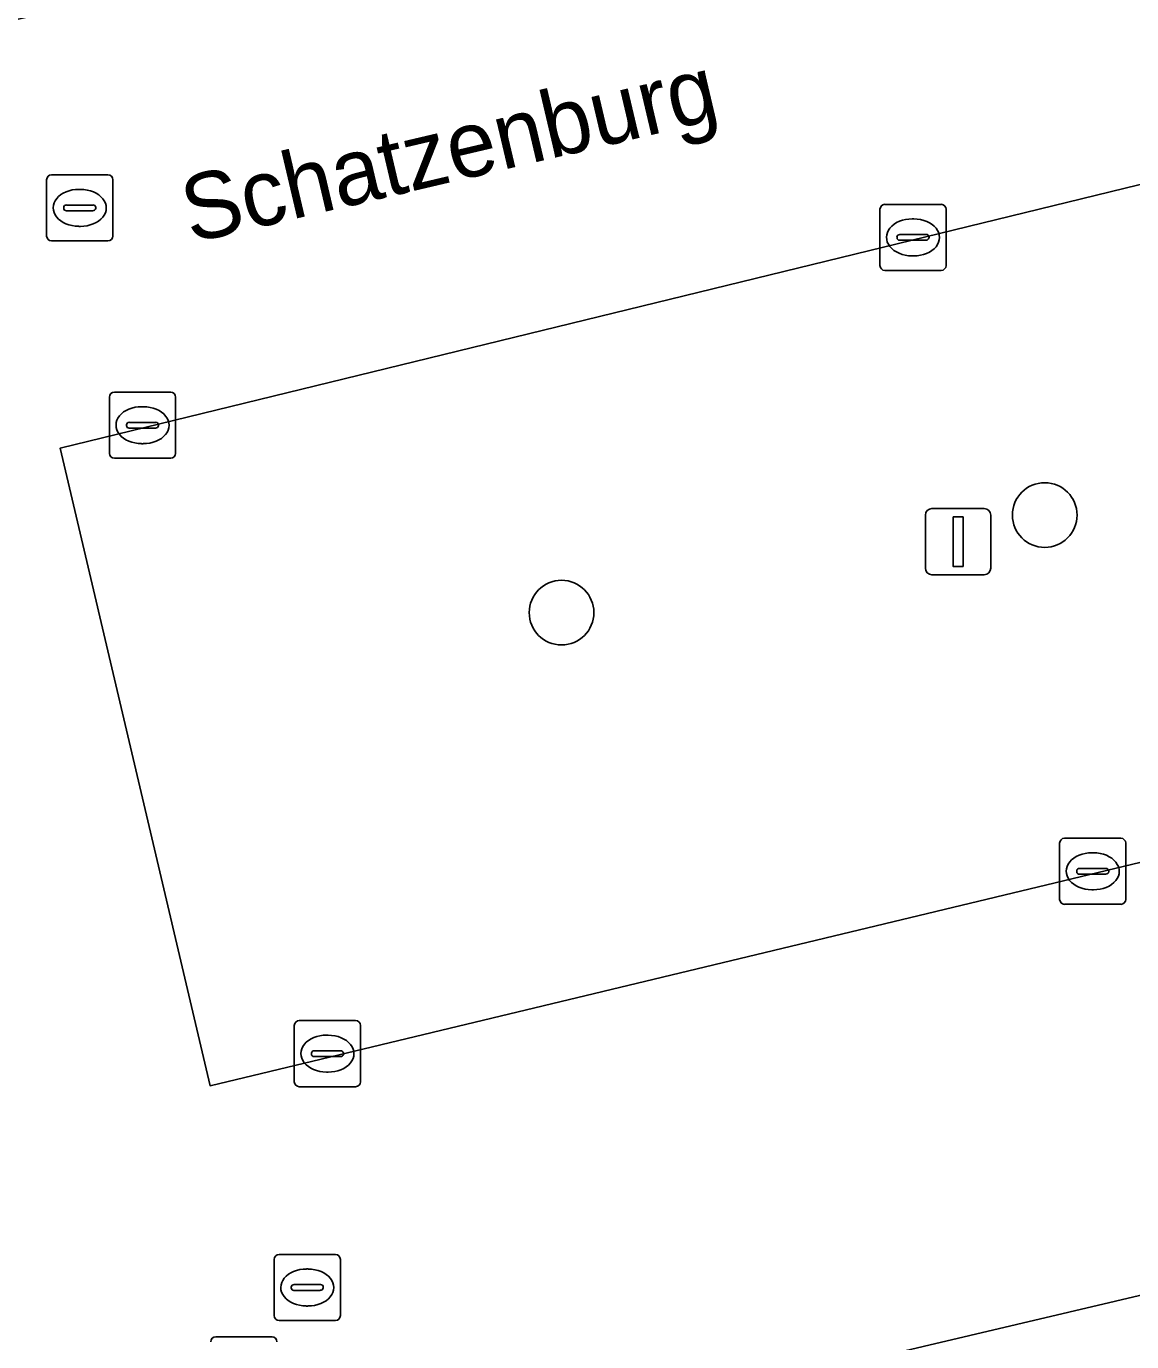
# Model space of a CAD drawing. Extents: x 158031 to 159244, y 380104 to 381214.
# Drawn here: x 158644.85 to 158661.57, y 380591.53 to 380611.43 of the extents above; entities that cross this region are included whole.
import ezdxf

# ---------------------------------------------------------------- set-up
doc = ezdxf.new("R2010")
doc.units = 0
for name, color, linetype in [('IMGEO_Boom', 7, 'Continuous'), ('IMGEO_Kolk', 7, 'Continuous'), ('IMGEO_Lichtmast', 7, 'Continuous'), ('IMGEO_Openbare_ruimte_label', 7, 'Continuous'), ('IMGEO_Parkeervlak_open', 7, 'Continuous'), ('IMGEO_Rijbaan_lokaal_open', 7, 'Continuous'), ('IMGEO_Rioolput', 7, 'Continuous'), ('IMGEO_Voetpad_open', 7, 'Continuous')]:
    doc.layers.add(name, color=color, linetype=linetype)

msp = doc.modelspace()

# ---------------------------------------------------------------- linework, layer by layer
at = {"layer": 'IMGEO_Boom'}
for centre in [(158660.256, 380604.036), (158652.948, 380602.56)]:
    msp.add_circle(centre, 0.489, dxfattribs=at)
at = {"layer": 'IMGEO_Kolk'}
for p, q in [((158657.838, 380608.737), (158658.69, 380608.737)), ((158657.763, 380607.811), (158657.763, 380608.663)), ((158658.251, 380608.517), (158658.276, 380608.517)), ((158658.764, 380608.663), (158658.764, 380607.811)), ((158658.022, 380608.231), (158658.022, 380608.243)), ((158658.46, 380608.194), (158658.062, 380608.194)), ((158658.065, 380608.28), (158658.463, 380608.28)), ((158658.506, 380608.243), (158658.506, 380608.231)), ((158658.274, 380607.957), (158658.249, 380607.957)), ((158658.69, 380607.737), (158657.838, 380607.737)), ((158646.11, 380604.97), (158646.11, 380605.822)), ((158646.185, 380605.896), (158647.037, 380605.896)), ((158647.111, 380605.822), (158647.111, 380604.97)), ((158646.598, 380605.676), (158646.623, 380605.676)), ((158646.369, 380605.39), (158646.369, 380605.402)), ((158646.807, 380605.353), (158646.409, 380605.353)), ((158646.412, 380605.439), (158646.81, 380605.439)), ((158646.853, 380605.402), (158646.853, 380605.39)), ((158646.621, 380605.116), (158646.596, 380605.116)), ((158647.037, 380604.896), (158646.185, 380604.896)), ((158660.481, 380598.221), (158660.481, 380599.073)), ((158660.556, 380599.147), (158661.408, 380599.147)), ((158661.482, 380599.073), (158661.482, 380598.221)), ((158660.969, 380598.927), (158660.994, 380598.927)), ((158660.74, 380598.641), (158660.74, 380598.653)), ((158661.178, 380598.604), (158660.78, 380598.604)), ((158660.783, 380598.69), (158661.181, 380598.69)), ((158661.224, 380598.653), (158661.224, 380598.641)), ((158660.992, 380598.367), (158660.967, 380598.367)), ((158661.408, 380598.147), (158660.556, 380598.147)), ((158648.981, 380596.388), (158649.833, 380596.388)), ((158648.906, 380595.462), (158648.906, 380596.314)), ((158649.907, 380596.314), (158649.907, 380595.462)), ((158649.394, 380596.168), (158649.419, 380596.168)), ((158649.165, 380595.882), (158649.165, 380595.894)), ((158649.603, 380595.845), (158649.205, 380595.845)), ((158649.208, 380595.931), (158649.606, 380595.931)), ((158649.649, 380595.894), (158649.649, 380595.882)), ((158649.417, 380595.608), (158649.392, 380595.608)), ((158649.833, 380595.388), (158648.981, 380595.388))]:
    msp.add_line(p, q, dxfattribs=at)
for points in [[(158657.838, 380608.737), (158658.69, 380608.737)], [(158657.763, 380607.811), (158657.763, 380608.663)], [(158658.764, 380608.663), (158658.764, 380607.811)], [(158658.69, 380607.737), (158657.838, 380607.737)], [(158646.11, 380604.97), (158646.11, 380605.822)], [(158646.185, 380605.896), (158647.037, 380605.896)], [(158647.111, 380605.822), (158647.111, 380604.97)], [(158647.037, 380604.896), (158646.185, 380604.896)], [(158660.481, 380598.221), (158660.481, 380599.073)], [(158660.556, 380599.147), (158661.408, 380599.147)], [(158661.482, 380599.073), (158661.482, 380598.221)], [(158661.408, 380598.147), (158660.556, 380598.147)], [(158648.981, 380596.388), (158649.833, 380596.388)], [(158648.906, 380595.462), (158648.906, 380596.314)], [(158649.907, 380596.314), (158649.907, 380595.462)], [(158649.833, 380595.388), (158648.981, 380595.388)]]:
    msp.add_lwpolyline(points, dxfattribs=at)
for centre, radius, start, end in [((158657.84, 380608.661), 0.0765, 91.552, 178.448), ((158657.84, 380608.661), 0.0765, 91.552, 178.448), ((158658.688, 380608.661), 0.0765, 1.552, 88.448), ((158658.688, 380608.661), 0.0765, 1.552, 88.448), ((158658.062, 380608.24), 0.0403, 85.8775, 175.7526), ((158658.059, 380608.23), 0.0366, 178.938, 274.7102), ((158658.463, 380608.237), 0.043, 264.8664, 352.4533), ((158658.467, 380608.242), 0.0386, 1.7309, 96.639), ((158657.84, 380607.813), 0.0765, 181.552, 268.448), ((158657.84, 380607.813), 0.0765, 181.552, 268.448), ((158658.688, 380607.813), 0.0765, 271.552, 358.448), ((158658.688, 380607.813), 0.0765, 271.552, 358.448), ((158646.187, 380605.82), 0.0765, 91.552, 178.448), ((158646.187, 380605.82), 0.0765, 91.552, 178.448), ((158647.035, 380605.82), 0.0765, 1.552, 88.448), ((158647.035, 380605.82), 0.0765, 1.552, 88.448), ((158646.409, 380605.399), 0.0403, 85.8775, 175.7526), ((158646.406, 380605.389), 0.0366, 178.938, 274.7102), ((158646.81, 380605.396), 0.043, 264.8664, 352.4533), ((158646.814, 380605.401), 0.0386, 1.7309, 96.639), ((158646.187, 380604.972), 0.0765, 181.552, 268.448), ((158646.187, 380604.972), 0.0765, 181.552, 268.448), ((158647.035, 380604.972), 0.0765, 271.552, 358.448), ((158647.035, 380604.972), 0.0765, 271.552, 358.448), ((158660.558, 380599.071), 0.0765, 91.552, 178.448), ((158660.558, 380599.071), 0.0765, 91.552, 178.448), ((158661.406, 380599.071), 0.0765, 1.552, 88.448), ((158661.406, 380599.071), 0.0765, 1.552, 88.448), ((158660.78, 380598.65), 0.0403, 85.8775, 175.7526), ((158660.777, 380598.64), 0.0366, 178.938, 274.7102), ((158661.181, 380598.647), 0.043, 264.8664, 352.4533), ((158661.185, 380598.652), 0.0386, 1.7309, 96.639), ((158660.558, 380598.223), 0.0765, 181.552, 268.448), ((158660.558, 380598.223), 0.0765, 181.552, 268.448), ((158661.406, 380598.223), 0.0765, 271.552, 358.448), ((158661.406, 380598.223), 0.0765, 271.552, 358.448), ((158648.983, 380596.312), 0.0765, 91.552, 178.448), ((158648.983, 380596.312), 0.0765, 91.552, 178.448), ((158649.831, 380596.312), 0.0765, 1.552, 88.448), ((158649.831, 380596.312), 0.0765, 1.552, 88.448), ((158649.205, 380595.891), 0.0403, 85.8775, 175.7526), ((158649.202, 380595.881), 0.0366, 178.938, 274.7102), ((158649.606, 380595.888), 0.043, 264.8664, 352.4533), ((158649.61, 380595.893), 0.0386, 1.7309, 96.639), ((158648.983, 380595.464), 0.0765, 181.552, 268.448), ((158648.983, 380595.464), 0.0765, 181.552, 268.448), ((158649.831, 380595.464), 0.0765, 271.552, 358.448), ((158649.831, 380595.464), 0.0765, 271.552, 358.448)]:
    msp.add_arc(centre, radius, start, end, dxfattribs=at)
for centre, major_axis, ratio, start_param, end_param in [((158658.25, 380608.237), (-0.387, 0.002), 0.722429, 4.712389, 7.853982), ((158658.275, 380608.237), (-0.39, 0.002), 0.717154, 1.570796, 4.712389), ((158646.597, 380605.396), (-0.387, 0.002), 0.722429, 4.712389, 7.853982), ((158646.622, 380605.396), (-0.39, 0.002), 0.717154, 1.570796, 4.712389), ((158660.968, 380598.647), (-0.387, 0.002), 0.722429, 4.712389, 7.853982), ((158660.993, 380598.647), (-0.39, 0.002), 0.717154, 1.570796, 4.712389), ((158649.393, 380595.888), (-0.387, 0.002), 0.722429, 4.712389, 7.853982), ((158649.418, 380595.888), (-0.39, 0.002), 0.717154, 1.570796, 4.712389)]:
    msp.add_ellipse(centre, major_axis=major_axis, ratio=ratio, start_param=start_param, end_param=end_param, dxfattribs=at)
at = {"layer": 'IMGEO_Lichtmast'}
for p, q in [((158658.451, 380603.234), (158658.451, 380604.034)), ((158658.451, 380604.034), (158658.451, 380603.234)), ((158658.551, 380604.134), (158659.341, 380604.134)), ((158659.341, 380604.134), (158658.551, 380604.134)), ((158659.441, 380604.034), (158659.441, 380603.234)), ((158659.441, 380603.234), (158659.441, 380604.034)), ((158659.341, 380603.134), (158658.551, 380603.134)), ((158658.551, 380603.134), (158659.341, 380603.134))]:
    msp.add_line(p, q, dxfattribs=at)
msp.add_lwpolyline([(158658.871, 380604.009), (158659.021, 380604.009), (158659.021, 380603.259), (158658.871, 380603.259), (158658.871, 380604.009)], dxfattribs=at)
for centre, start, end in [((158658.551, 380604.034), 90, 180), ((158658.551, 380604.034), 90, 180), ((158659.341, 380604.034), 0, 90), ((158659.341, 380604.034), 360, 90), ((158658.551, 380603.234), 180, 270), ((158658.551, 380603.234), 180, 270), ((158659.341, 380603.234), 270, 0), ((158659.341, 380603.234), 270, 0)]:
    msp.add_arc(centre, 0.1, start, end, dxfattribs=at)
at = {"layer": 'IMGEO_Parkeervlak_open'}
msp.add_lwpolyline([(158662.959, 380609.345), (158645.363, 380605.047), (158647.633, 380595.402), (158665.451, 380599.684)], dxfattribs=at)
at = {"layer": 'IMGEO_Rijbaan_lokaal_open'}
msp.add_lwpolyline([(158674.8, 380595.318), (158681.44, 380567.252), (158682.048, 380564.681), (158687.531, 380566.04), (158675.144, 380618.798), (158674.853, 380618.727), (158646.289, 380611.903), (158642.774, 380611.091), (158641.644, 380615.902), (158637.085, 380614.819), (158638.238, 380610.014), (158643.37, 380588.22), (158643.438, 380587.928)], close=True, dxfattribs=at)
msp.add_lwpolyline([(158671.311, 380601.141), (158665.451, 380599.684), (158647.633, 380595.402), (158645.363, 380605.047), (158662.959, 380609.345), (158668.944, 380610.78)], dxfattribs=at)
at = {"layer": 'IMGEO_Rioolput'}
for p, q in [((158645.235, 380609.184), (158646.087, 380609.184)), ((158645.16, 380608.258), (158645.16, 380609.11)), ((158645.648, 380608.964), (158645.673, 380608.964)), ((158646.161, 380609.11), (158646.161, 380608.258)), ((158645.462, 380608.727), (158645.86, 380608.727)), ((158645.419, 380608.678), (158645.419, 380608.69)), ((158645.857, 380608.641), (158645.459, 380608.641)), ((158645.903, 380608.69), (158645.903, 380608.678)), ((158645.671, 380608.404), (158645.646, 380608.404)), ((158646.087, 380608.184), (158645.235, 380608.184)), ((158648.677, 380592.85), (158649.529, 380592.85)), ((158648.602, 380591.924), (158648.602, 380592.776)), ((158649.09, 380592.63), (158649.115, 380592.63)), ((158649.603, 380592.776), (158649.603, 380591.924)), ((158648.861, 380592.344), (158648.861, 380592.356)), ((158649.299, 380592.307), (158648.901, 380592.307)), ((158648.904, 380592.393), (158649.302, 380592.393)), ((158649.345, 380592.356), (158649.345, 380592.344)), ((158649.113, 380592.07), (158649.088, 380592.07)), ((158649.529, 380591.85), (158648.677, 380591.85)), ((158647.718, 380591.604), (158648.57, 380591.604))]:
    msp.add_line(p, q, dxfattribs=at)
for points in [[(158645.235, 380609.184), (158646.087, 380609.184)], [(158645.16, 380608.258), (158645.16, 380609.11)], [(158646.161, 380609.11), (158646.161, 380608.258)], [(158646.087, 380608.184), (158645.235, 380608.184)], [(158648.677, 380592.85), (158649.529, 380592.85)], [(158648.602, 380591.924), (158648.602, 380592.776)], [(158649.603, 380592.776), (158649.603, 380591.924)], [(158649.529, 380591.85), (158648.677, 380591.85)], [(158647.718, 380591.604), (158648.57, 380591.604)]]:
    msp.add_lwpolyline(points, dxfattribs=at)
for centre, radius, start, end in [((158645.237, 380609.108), 0.0765, 91.552, 178.448), ((158645.237, 380609.108), 0.0765, 91.552, 178.448), ((158646.085, 380609.108), 0.0765, 1.552, 88.448), ((158646.085, 380609.108), 0.0765, 1.552, 88.448), ((158645.459, 380608.687), 0.0403, 85.8775, 175.7526), ((158645.864, 380608.689), 0.0386, 1.7309, 96.639), ((158645.456, 380608.677), 0.0366, 178.938, 274.7102), ((158645.86, 380608.684), 0.043, 264.8664, 352.4533), ((158645.237, 380608.26), 0.0765, 181.552, 268.448), ((158645.237, 380608.26), 0.0765, 181.552, 268.448), ((158646.085, 380608.26), 0.0765, 271.552, 358.448), ((158646.085, 380608.26), 0.0765, 271.552, 358.448), ((158648.679, 380592.774), 0.0765, 91.552, 178.448), ((158648.679, 380592.774), 0.0765, 91.552, 178.448), ((158649.527, 380592.774), 0.0765, 1.552, 88.448), ((158649.527, 380592.774), 0.0765, 1.552, 88.448), ((158648.901, 380592.353), 0.0403, 85.8775, 175.7526), ((158648.898, 380592.343), 0.0366, 178.938, 274.7102), ((158649.302, 380592.35), 0.043, 264.8664, 352.4533), ((158649.306, 380592.355), 0.0386, 1.7309, 96.639), ((158648.679, 380591.926), 0.0765, 181.552, 268.448), ((158648.679, 380591.926), 0.0765, 181.552, 268.448), ((158649.527, 380591.926), 0.0765, 271.552, 358.448), ((158649.527, 380591.926), 0.0765, 271.552, 358.448), ((158647.72, 380591.528), 0.0765, 91.552, 178.448), ((158647.72, 380591.528), 0.0765, 91.552, 178.448), ((158648.568, 380591.528), 0.0765, 1.552, 88.448), ((158648.568, 380591.528), 0.0765, 1.552, 88.448)]:
    msp.add_arc(centre, radius, start, end, dxfattribs=at)
for centre, major_axis, ratio, start_param, end_param in [((158645.647, 380608.684), (-0.387, 0.002), 0.722429, 4.712389, 7.853982), ((158645.672, 380608.684), (-0.39, 0.002), 0.717154, 1.570796, 4.712389), ((158649.089, 380592.35), (-0.387, 0.002), 0.722429, 4.712389, 7.853982), ((158649.114, 380592.35), (-0.39, 0.002), 0.717154, 1.570796, 4.712389)]:
    msp.add_ellipse(centre, major_axis=major_axis, ratio=ratio, start_param=start_param, end_param=end_param, dxfattribs=at)
at = {"layer": 'IMGEO_Voetpad_open'}
msp.add_lwpolyline([(158643.365, 380584.377), (158647.621, 380585.372), (158648.817, 380585.646), (158652.938, 380586.622), (158657.058, 380587.598), (158658.261, 380587.883), (158662.392, 380588.854), (158669.274, 380590.443), (158670.036, 380587.207), (158673.036, 380587.921), (158675.45, 380577.785), (158676.122, 380574.962), (158676.098, 380574.956), (158678.049, 380566.443), (158681.44, 380567.252), (158674.8, 380595.318), (158643.438, 380587.928)], dxfattribs=at)

# ---------------------------------------------------------------- texts
at = {"layer": 'IMGEO_Openbare_ruimte_label'}
msp.add_text('Schatzenburg', height=1, rotation=13.2438, dxfattribs=at).set_placement((158647.341, 380608.146))

doc.saveas('drawing.dxf')
